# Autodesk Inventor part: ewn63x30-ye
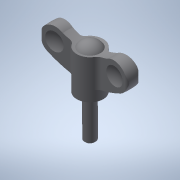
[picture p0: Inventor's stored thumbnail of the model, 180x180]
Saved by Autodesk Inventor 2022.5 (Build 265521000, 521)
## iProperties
Created: 2017-05
Part Number: ewn63x30-ye
Material: 一般
Document SubType Name: Modeling
Designer: imaocorp
Density: 1 g/cm^3
Appearance: 既定
Author: imaocorp
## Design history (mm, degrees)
node "ewn63x30-ye.x_t1"
node "ewn63x30-ye"
node "Base1"
